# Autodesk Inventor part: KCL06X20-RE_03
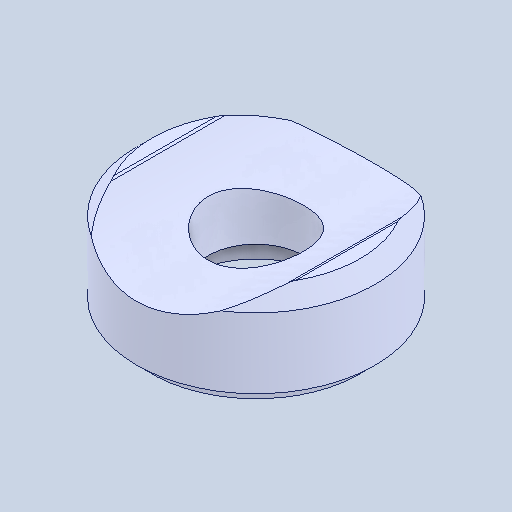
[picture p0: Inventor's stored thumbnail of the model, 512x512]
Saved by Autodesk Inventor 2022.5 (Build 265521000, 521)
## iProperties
Created: 2024-08
Part Number: KCL06X20-RE_03
Material: 一般
Document SubType Name: Modeling
Designer: ImaoCorp
Density: 1 g/cm^3
Appearance: 既定
Author: ImaoCorp
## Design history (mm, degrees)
feature "KCL06X20-RE_03"
node "ソリッド1"
